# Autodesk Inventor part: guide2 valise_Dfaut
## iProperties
Created: 2007-07
Part Number: guide2 valise_Dfaut
Document SubType Name: Modeling
Designer: EF
Density: 1 g/cm^3
Author: EF
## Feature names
1. Base1
